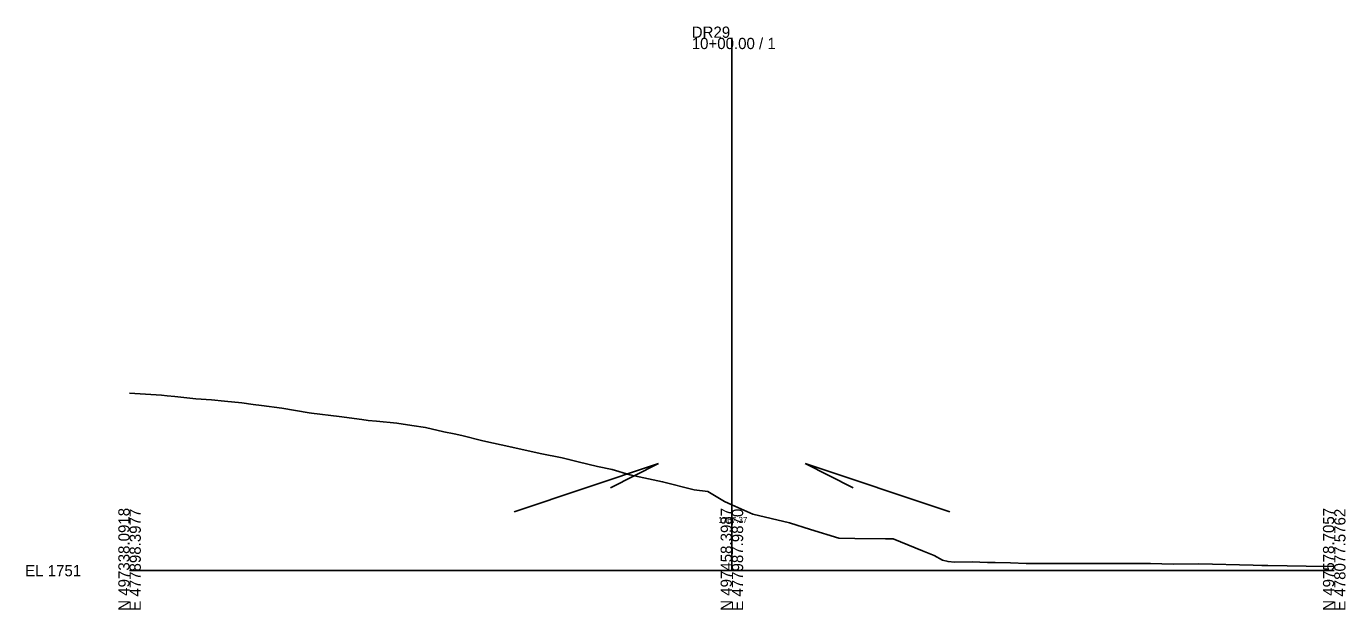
# Model space of a CAD drawing. Extents: x -26 to 303, y -10 to 4734.
# Drawn here: x -25.7 to 302.8, y -9.7 to 135.4 of the extents above; entities that cross this region are included whole.
import ezdxf

# ---------------------------------------------------------------- set-up
doc = ezdxf.new("R2010")
doc.units = 0
for name, color, linetype in [('Exist Cross Section Cell', 7, 'Continuous'), ('Exist XS Center Line Elevation Label', 7, 'Continuous'), ('Exist XS Ground Line', 7, 'Continuous'), ('Scratch_Level_3', 7, 'Continuous')]:
    doc.layers.add(name, color=color, linetype=linetype)

msp = doc.modelspace()

# ---------------------------------------------------------------- linework, layer by layer
at = {"layer": 'Exist Cross Section Cell'}
for p, q in [((150, 0), (150, 132.57)), ((0, 0), (150, 0)), ((150, 0), (300, 0))]:
    msp.add_line(p, q, dxfattribs=at)
at = {"layer": 'Exist XS Ground Line'}
msp.add_lwpolyline([(0, 44.19), (7.94, 43.68), (9.35, 43.51), (11.25, 43.32), (16.5, 42.74), (20.41, 42.48), (23.65, 42.18), (27.99, 41.72), (30.8, 41.36), (32.88, 41.1), (37.94, 40.41), (44.74, 39.23), (45.35, 39.15), (52.24, 38.39), (57.82, 37.58), (59.39, 37.37), (61.49, 37.21), (66.53, 36.7), (70.29, 36.13), (73.68, 35.61), (78.23, 34.54), (80.83, 34.04), (82.76, 33.59), (87.98, 32.3), (95.23, 30.72), (102.27, 29.13), (107.7, 28.06), (109.42, 27.69), (111.73, 27.09), (116.57, 25.89), (120.17, 25.13), (124.58, 23.86), (132.73, 22.12), (140.57, 20.14), (143.98, 19.73), (148.18, 17.17), (150, 16.37), (155.18, 14.09), (164.37, 11.9), (169.57, 10.24), (176.66, 8.05), (180.62, 8.02), (188.23, 7.92), (190.18, 7.9), (197.46, 4.96), (200.35, 3.74), (202.44, 2.62), (203.85, 2.27), (205.45, 2.1), (209.82, 2.16), (213.62, 2.02), (215.53, 2), (219.39, 1.92), (223.29, 1.81), (230.75, 1.74), (233.07, 1.8), (236.79, 1.77), (245.73, 1.79), (246.05, 1.78), (254.27, 1.75), (259.87, 1.65), (266.26, 1.68), (279.83, 1.34), (281.94, 1.29), (283.48, 1.28), (297.83, 1.02), (299.67, 1.11), (300, 1.1)], dxfattribs=at)
at = {"layer": 'Scratch_Level_3'}
for p, q in [((131.76, 26.63), (95.76, 14.63)), ((131.76, 26.63), (119.76, 20.63)), ((168.24, 26.63), (204.24, 14.63)), ((168.24, 26.63), (180.24, 20.63))]:
    msp.add_line(p, q, dxfattribs=at)

# ---------------------------------------------------------------- texts
at = {"layer": 'Exist Cross Section Cell'}
for s, p in [('DR29', (140, 132.57)), ('10+00.00 / 1', (140, 129.77)), ('EL 1751', (-26, -1.4))]:
    msp.add_text(s, height=2.8, dxfattribs=at).set_placement(p)
for s, p in [('N 497338.0918', (0, -10)), ('E 477898.3977', (2.8, -10)), ('N 497458.3987', (150, -10)), ('E 477987.9870', (152.8, -10)), ('N 497578.7057', (300, -10)), ('E 478077.5762', (302.8, -10))]:
    msp.add_text(s, height=2.8, rotation=90, dxfattribs=at).set_placement(p)
at = {"layer": 'Exist XS Center Line Elevation Label'}
msp.add_text('1767.37', height=1.5, dxfattribs=at).set_placement((146.61, 11.87))

doc.saveas('drawing.dxf')
